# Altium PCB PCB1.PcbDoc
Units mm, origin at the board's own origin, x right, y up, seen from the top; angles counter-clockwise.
Board outline 145 x 75 mm, 2 copper layers (Top Layer, Bottom Layer); 34 components, 27 nets, 127 pads, 4 vias.
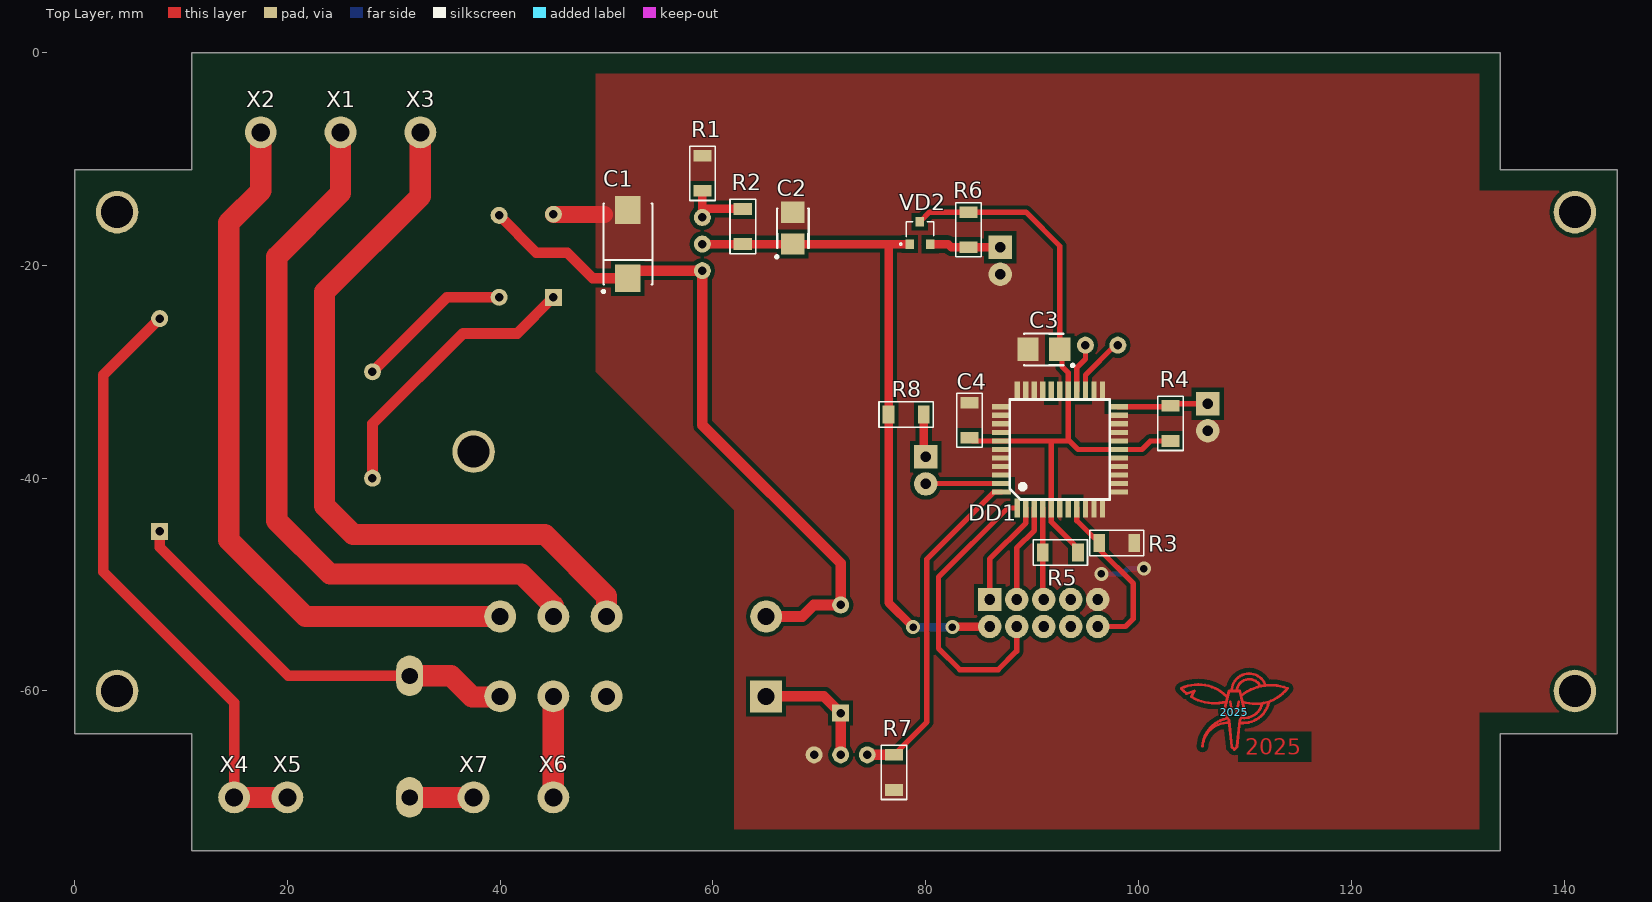
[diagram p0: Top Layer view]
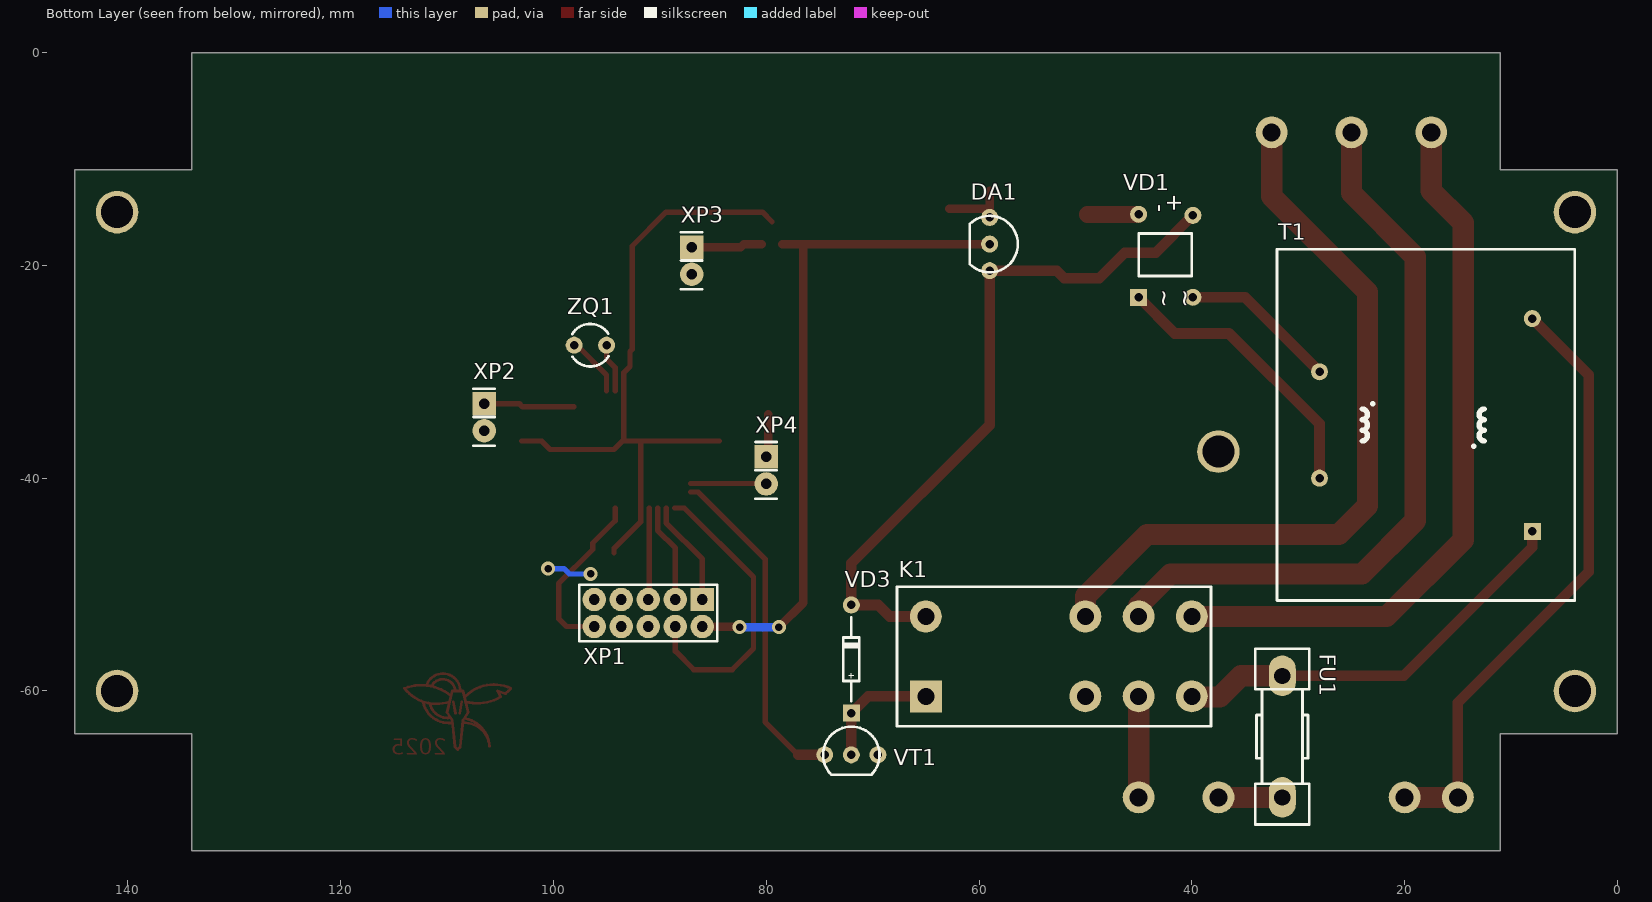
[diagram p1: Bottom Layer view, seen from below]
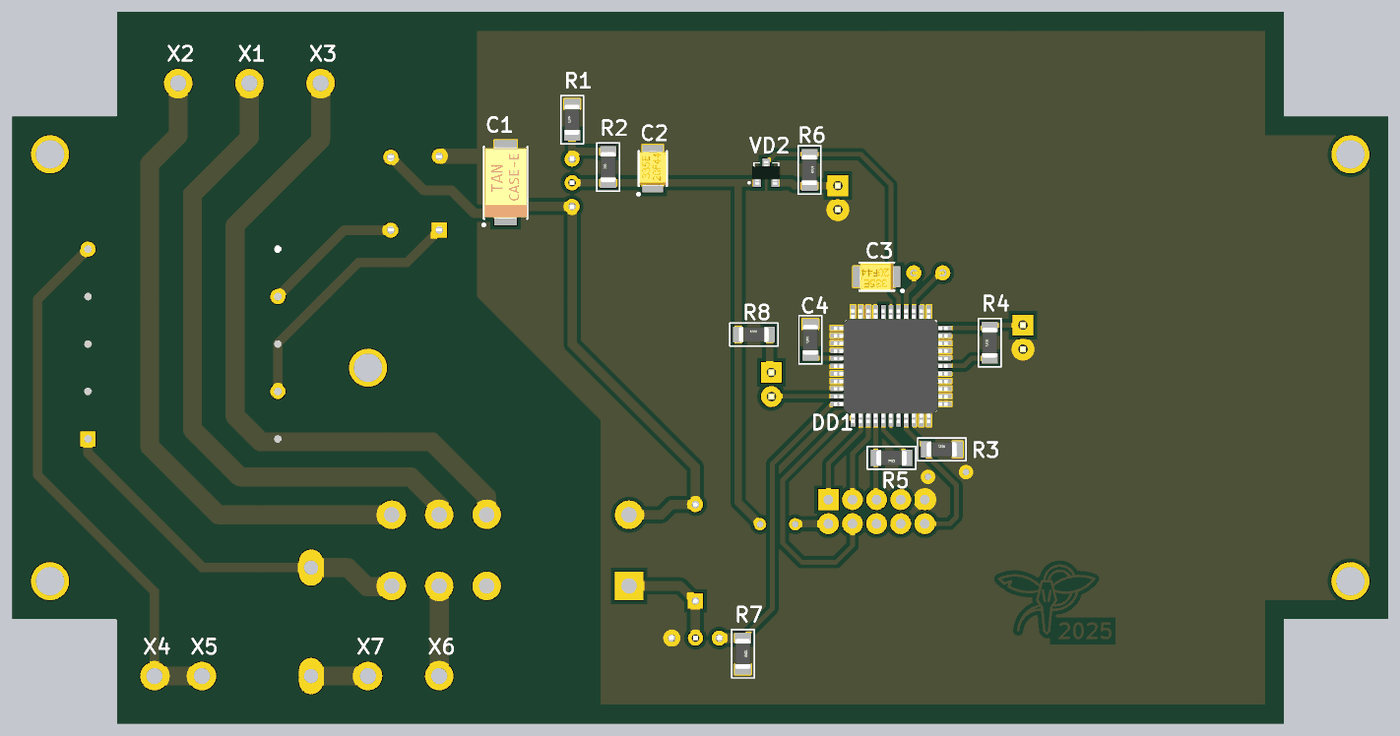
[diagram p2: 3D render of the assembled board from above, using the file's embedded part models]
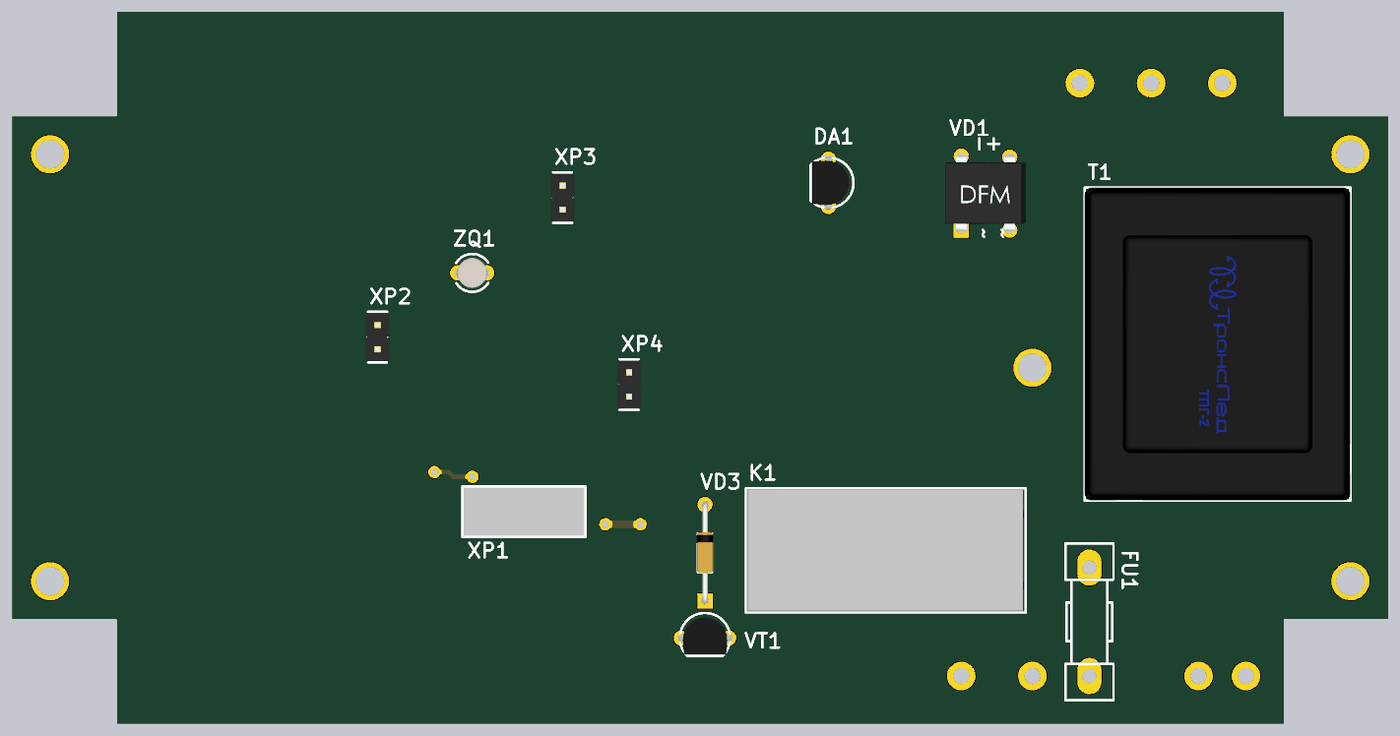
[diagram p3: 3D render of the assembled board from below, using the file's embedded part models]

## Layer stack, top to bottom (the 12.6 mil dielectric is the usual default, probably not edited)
Top Layer: signal copper 0.0356
Dielectric: dielectric 0.32, FR-4, Dk 4.8
Bottom Layer: signal copper 0.0356

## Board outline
0,-64 11,-64 11,-75 134,-75 134,-64 145,-64 145,-11 134,-11 134,0 11,0 11,-11 0,-11

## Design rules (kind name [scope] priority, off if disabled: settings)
Clearance Clearance_poly [InPolygon] p1: gap=0.4
Clearance [All] p2: gap=0.2
ComponentClearance [All] p1: gap=0.25 collisioncheckmode=3 verticalgap=0.25 showdistances=FALSE
DiffPairsRouting [All] p1: maxlimit=1 minlimit=0.2 mostfreqgap=0.8 maxuncoupledlength=10
Height [All] p1: minheight=0 maxheight=45 prefheight=12.5
PolygonConnect [All] p1: connectstyle=Direct reliefconductorwidth=0.35 reliefentries=4 polygonreliefangle="90 Angle"
RoutingVias [All] p1: holewidth=0.8 width=1.2 viastyle="Through Hole" minholewidth=0.7 minwidth=1 maxholewidth=1 maxwidth=1.5
SilkscreenOverComponentPads [All] p1: minsilkscreentomaskgap=0.254
SolderMaskExpansion [All] p1: expansion=0.102
Width [All] p1: maxlimit=3 minlimit=0.3 preferedwidth=0.5
24 further rules are at their usual default settings.

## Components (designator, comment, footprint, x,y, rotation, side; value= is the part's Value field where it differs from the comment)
2025 "2025" "Rat's logo" 109,-62 r0 top
C1 "Type E" "Type E" 52,-18 r90 top
C2 "Type B" "Type B" 67.5,-16.5 r90 top
C3 "Type B" "Type B" 91.1,-27.9 r180 top
C4 "C_1206" RC_1206 84.1,-36.2 r90 top
DA1 "LM317L" TO-92 59,-18 r270 bottom
DD1 "К1946ВМ014" TQFP-44 88.6,-42.8 r90 top
FU1 "Предохранитель" ВП2-1 31.5,-70 r90 bottom
K1 "RP3" RP3 65,-60.5 r0 bottom
R1 "R_1206" RC_1206 59,-13 r90 top
R2 "R_1206" RC_1206 62.8,-18 r90 top
R3 "R_1206" RC_1206 96.3,-46.1 r0 top
R4 "R_1206" RC_1206 103,-36.5 r90 top
R5 "R_1206" RC_1206 94.3,-47 r180 top
R6 "R_1206" RC_1206 84,-15 r270 top
R7 "R_1206" RC_1206 77,-66 r270 top
R8 "R_1206" RC_1206 76.5,-34 r0 top
T1 "ТПК-2" ТПГ-2 8,-45 r0 bottom
VD1 "КД906" DB-1 45,-23 r90 bottom
VD2 "КДШ160БС9" SOT-23 78.5,-18 r0 top
VD3 "КД510" DO-35 72,-57 r90 bottom
VT1 "КП501" TO-92 72,-66 r180 bottom
X1 "Клемма 1,7 мм" "Клемма 1,7 мм" 25,-7.5 r0 top
X2 "Клемма 1,7 мм" "Клемма 1,7 мм" 17.5,-7.5 r0 top
X3 "Клемма 1,7 мм" "Клемма 1,7 мм" 32.5,-7.5 r0 top
X4 "Клемма 1,7 мм" "Клемма 1,7 мм" 15,-70 r0 top
X5 "Клемма 1,7 мм" "Клемма 1,7 мм" 20,-70 r0 top
X6 "Клемма 1,7 мм" "Клемма 1,7 мм" 45,-70 r0 top
X7 "Клемма 1,7 мм" "Клемма 1,7 мм" 37.5,-70 r0 top
XP1 "IDC_progr" IDC-10MS 86,-51.4 r0 bottom
XP2 "Button" PLS-2 106.5,-33 r270 bottom
XP3 "Pow" PLS-2 87,-18.3 r270 bottom
XP4 "LED" PLS-2 80,-38 r270 bottom
ZQ1 "DT-38T" DT-38T 95,-27.5 r90 bottom

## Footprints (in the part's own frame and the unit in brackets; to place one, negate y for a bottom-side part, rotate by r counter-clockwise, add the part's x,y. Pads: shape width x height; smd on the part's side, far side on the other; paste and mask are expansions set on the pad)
DB-1 [mm]
  rect 1.6x1.6 hole 0.8: 1(0,0)
  round 1.6 hole 0.8: 2(0,-5.1) 3(7.7,-5.1) 4(7.8,0)
  silkscreen extent 2,-5 6,0, body extent -0.1,-6.81 7.9,1.7, height 4.75
DO-35 [mm]
  rect 1.6x1.6 hole 0.8: 1(-5.084,0)
  round 1.6 hole 0.8: 2(5.084,0)
  silkscreen extent -3.94,-0.75 3.94,0.75, body extent -5.35,-0.89 5.34,0.86, height 2.15
DT-38T [mm]
  round 1.6 hole 0.8: 1(0,0) 2(0,3.048)
  silkscreen extent -2,-0.18 2,3.23, body extent -1.6,-0.2 1.6,3.25, height 9.77
IDC-10MS [mm]
  rect 2.2x2.2 hole 1: 1(0,0)
  round 2.2 hole 1: 2(0,2.54) 3(2.54,0) 4(2.54,2.54) 5(5.08,0) 6(5.08,2.54) 7(7.62,0) 8(7.62,2.54) 9(10.16,0) 10(10.16,2.54)
  silkscreen extent -1.4,-1.4 11.56,3.94, body extent -1.27,-1.27 11.43,3.81, height 8.54
PLS-2 [mm]
  rect 2.2x2.2 hole 1: 1(0,0)
  round 2.2 hole 1: 2(2.54,0)
  silkscreen extent -1.4,-1 3.94,1, body extent -1.27,-1.27 3.81,1.27, height 8.54
"Rat's logo" [mm]
  Top Layer lines w0.254: -4.516,1.786 cw(c-1.875,5.025) -5,2.25 cw(c-3.402,-1.109) -0.75,1.5 ; -4.5,1.75 -3.75,2 -4,1.5 ; -4.033,1.446 ccw(c-1.875,5.025) -0.75,1 ; -0.8,-0.6 ccw(c-0.153,-3.378) -3,-3.2 cw(c-0.65,-3.35) -0.5,-1 ; -0.4,1 -0.2,-0.1 ; -0.238,2.147 cw(c1.384,2.012) 2.9,2.6 ; 0.2,-0.1 0.4,1 ; 0.239,2.148 cw(c1.394,1.929) 2.395,2.546 ; 0.6,-1 ccw(c0.831,1.445) 3.23,0.923 ; 0.652,1.562 cw(c3.411,-1.797) 5,2.25 cw(c2,4.6) 0.75,1 ; 0.711,-0.52 ccw(c0.937,1.169) 2.6,0.8 ; -1,0 -0.5,2 0.5,2 1,0 0.5,-0.75 0.25,-3.25 0,-3.5 -0.25,-3.25 -0.5,-0.75 -1,0
RC_1206 [mm]
  rect 1.1x1.7 smd: 1(0,0) 2(3.3,0)
  silkscreen extent -0.9,-1.2 4.2,1.2, body extent 0.05,-0.8 3.25,0.8, height 1
RP3 [mm]
  rect 3x3 hole 1.6: 1(0,0)
  round 3 hole 1.6: 2(0,-7.5) 3(-20,0) 4(-15,0) 5(-25,0) 6(-20,-7.5) 7(-15,-7.5) 8(-25,-7.5)
  silkscreen extent -26.8,-10.3 2.7,2.8, body extent -26.5,-10.1 2.5,2.6, height 15.7
SOT-23 [mm]
  rect 0.8x0.9 smd: 1(0,0) 2(1.9,0) 3(0.95,2.1)
  silkscreen extent -0.95,-0.1 2.25,2.1, body extent -0.55,-0.2 2.45,2.3, height 1.05
TO-92 [mm]
  round 1.6 hole 0.8: 1(-2.5,0) 2(0,0) 3(2.5,0)
  silkscreen extent -2.65,-1.88 2.65,2.65, body extent -2.8,-1.75 2.8,2.18, height 9.7
TQFP-44 [mm]
  rect 1.8x0.5 smd: 1(0,0) 2(0,-0.8) 3(0,-1.6) 4(0,-2.4) 5(0,-3.2) 6(0,-4) 7(0,-4.8) 8(0,-5.6) 9(0,-6.4) 10(0,-7.2) 11(0,-8) 23(11,-8) 24(11,-7.2) 25(11,-6.4) 26(11,-5.6) 27(11,-4.8) 28(11,-4) 29(11,-3.2) 30(11,-2.4) 31(11,-1.6) 32(11,-0.8) 33(11,0)
  rect 0.5x1.8 smd: 12(1.5,-9.5) 13(2.3,-9.5) 14(3.1,-9.5) 15(3.9,-9.5) 16(4.7,-9.5) 17(5.5,-9.5) 18(6.3,-9.5) 19(7.1,-9.5) 20(7.9,-9.5) 21(8.7,-9.5) 22(9.5,-9.5) 34(9.5,1.5) 35(8.7,1.5) 36(7.9,1.5) 37(7.1,1.5) 38(6.3,1.5) 39(5.5,1.5) 40(4.7,1.5) 41(3.9,1.5) 42(3.1,1.5) 43(2.3,1.5) 44(1.5,1.5)
  silkscreen extent 0.8,-8.7 10.2,0.7, body extent -0.54,-9.97 11.46,2.03, height 1.1
"Type B" [mm]
  rect 2x2.2 smd: 1(-1.5,0) 2(1.5,0)
  silkscreen extent -2.82,-1.5 1.85,1.62, body extent -1.83,-1.4 1.83,1.4, height 1.89
"Type E" [mm]
  rect 2.6x2.4 smd: 1(-3.2,0) 2(3.2,0)
  silkscreen extent -4.57,-2.3 3.8,2.42, body extent -3.76,-2.25 3.76,2.25, height 4.1
ВП2-1 [mm]
  oval 3.81x2.54 hole 1.508: 1(0,0) 2(11.43,0)
  silkscreen extent -2.54,-2.54 13.97,2.54, body extent -2.42,-2.1 13.88,2.1, height 0.9
"Клемма 1,7 мм" [mm]
  round 3 hole 1.7: 1(0,0)
ТПГ-2 [mm]
  rect 1.6x1.6 hole 0.8: 1(0,0)
  round 1.6 hole 0.8: 5(0,-20) 7(20,-15) 9(20,-5)
  silkscreen extent -4,-26.5 24,6.5, body extent -4,-26.5 24,6.5, height 29.5

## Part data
VD1: library part DB102
VD3: library part 1N4148

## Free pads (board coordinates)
  round 4 hole 3 unplated: 0(4,-60) 0(4,-15) 0(37.5,-37.5) 0(141,-60) 0(141,-15)

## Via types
v1: diameter 1.3, hole 0.7, Top Layer to Bottom Layer, 4 vias

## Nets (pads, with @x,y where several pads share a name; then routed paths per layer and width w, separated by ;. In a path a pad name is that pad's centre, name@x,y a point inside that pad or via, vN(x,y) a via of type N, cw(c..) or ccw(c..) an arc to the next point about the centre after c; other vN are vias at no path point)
GND: C1.2 C2.2 C3.2 C4.2 DD1.6 DD1.9 DD1.10 DD1.11 DD1.12 DD1.13 DD1.14 DD1.15 DD1.16 DD1.18 DD1.19 DD1.20 DD1.21 DD1.23 DD1.24 DD1.28 DD1.30 DD1.31 DD1.32 DD1.33 DD1.34 DD1.35 DD1.36 DD1.37 DD1.39 DD1.40 DD1.41 DD1.42 R1.2 R3.2 R7.2 VD1.4 VT1.3 XP1.9 XP2.2 XP3.2 | length 9
  Top Layer w1.6: VD1.4 49.8,-15.2
  Bottom Layer w0.5: v1(96.5,-49) 98.5,-49 99,-48.5 v1(100.5,-48.5)
NetDA1_1: DA1.1 R1.1 R2.2 | length 6.3
  Top Layer w0.8: DA1.1 R1.1 ; 59,-14.7 R2.2
NetDD1_1: DD1.1 XP1.4 | length 28
  Top Layer w0.5: XP1.4 88.54,-56.26 86.8,-58 83.2,-58 81.2,-56 81.2,-49.3 87.7,-42.8 DD1.1
NetDD1_2: DD1.2 XP1.1 | length 10
  Top Layer w0.5: XP1.1 86,-47.6 89.4,-44.2 DD1.2
NetDD1_3: DD1.3 XP1.3 | length 9.3
  Top Layer w0.5: XP1.3 88.54,-46.56 90.2,-44.9 DD1.3
NetDD1_4: DD1.4 R5.2 XP1.5 | length 8.5
  Top Layer w0.5: XP1.5@91,-51.32 R5.2 DD1.4
NetDD1_8: DD1.8 R3.1 XP1.10 | length 16.2
  Top Layer w0.5: DD1.8 94.2,-44 R3.1 96.3,-46.7 99.5,-49.9 99.5,-53.2 98.76,-53.94 XP1.10
NetDD1_22: DD1.22 R4.2 XP2.1 | length 8.5
  Top Layer w0.5: DD1.22 102.9,-33.3 R4.2 103.2,-33 XP2.1
NetDD1_25: DD1.25 ZQ1.2 | length 5.7
  Top Layer w0.5: DD1.25 95,-30.3 97.8,-27.5 ZQ1.2
NetDD1_26: DD1.26 ZQ1.1 | length 4.6
  Top Layer w0.5: DD1.26 94.2,-29.6 95,-28.8 ZQ1.1
NetDD1_43: DD1.43 XP4.2 | length 7.1
  Top Layer w0.5: XP4.2@80.04,-40.5 DD1.43
NetDD1_44: DD1.44 R7.1 VT1.1 | length 31.8
  Top Layer w0.5: R7.1 80.1,-62.9 80.1,-47.6 86.4,-41.3 DD1.44
  Top Layer w1: VT1.1 R7.1
NetFU1_1: FU1.1 X7.1 | length 6
  Top Layer w2: FU1.1 X7.1
NetFU1_2: FU1.2 K1.5 T1.1 | length 39.3
  Top Layer w1: T1.1 8,-46.5 20.07,-58.57 FU1.2
  Top Layer w2: FU1.2 35.37,-58.57 37.37,-60.57 K1.5@39.93,-60.57
NetK1_1: K1.1 VD3.1 VT1.2 | length 11.6
  Top Layer w1: K1.1 70.417,-60.5 VD3.1 VT1.2
NetK1_3: K1.3 X6.1 | length 9.5
  Top Layer w2: X6.1 K1.3
NetK1_6: K1.6 X1.1 | length 69.3
  Top Layer w2: X1.1 25,-13.2 19,-19.2 19,-44 24,-49 42,-49 45,-52 K1.6
NetK1_7: K1.7 X3.1 | length 70.7
  Top Layer w2: X3.1 32.5,-13.5 23.5,-22.5 23.5,-42.6 26.2,-45.3 44.2,-45.3 50,-51.1 K1.7
NetK1_8: K1.8 X2.1 | length 68
  Top Layer w2: X2.1 17.5,-13 14.5,-16 14.5,-45.8 21.7,-53 K1.8
NetR6_2: R6.2 VD2.2 XP3.1 | length 6.7
  Top Layer w0.8: VD2.2 82.1,-18 82.4,-18.3 R6.2 XP3.1
NetR8_2: R8.2 XP4.1 | length 3.8
  Top Layer w0.8: XP4.1@79.8,-37.8 R8.2
NetT1_5: T1.5 X4.1 X5.1 | length 57.3
  Top Layer w1: T1.5 2.7,-30.3 2.7,-48.8 15,-61.1 X4.1
  Top Layer w2: X4.1 X5.1
NetT1_7: T1.7 VD1.2 | length 14.8
  Top Layer w1: T1.7 35,-23 VD1.2
NetT1_9: T1.9 VD1.1 | length 27
  Top Layer w1: T1.9 28,-34.9 36.5,-26.4 41.6,-26.4 VD1.1
VCC: C2.1 DA1.2 R2.1 R8.1 VD2.1 XP1.2 | length 63.5
  Top Layer w0.8: DA1.2 R2.1 VD2.1 ; 76.5,-18.1 R8.1 76.5,-51.7 v1(78.8,-54) ; v1@82.56,-53.94 XP1.2
  Bottom Layer w0.8: v1(78.8,-54) v1(82.5,-54)
VH: C1.1 DA1.3 K1.2 VD1.3 VD3.2 | length 66.1
  Top Layer w1: VD1.3 43.4,-18.8 46.3,-18.8 48.7,-21.2 C1.1 52.7,-20.5 DA1.3 59,-35 72,-48 VD3.2 69.484,-51.917 68.4,-53 K1.2
VMCU: C3.1 C4.1 DD1.5 DD1.17 DD1.27 DD1.38 R4.1 R5.1 R6.1 VD2.3 | length 64.2
  Top Layer w0.5: VD2.3 80.35,-15 R6.1 89.4,-15 92.6,-18.2 C3.1 92.8,-28.1 92.8,-29.5 93.4,-30.1 DD1.27 93.4,-36.4 ; C4.1@84.4,-36.5 DD1.38 93.5,-36.5 94.3,-37.3 DD1.17 100.3,-37.3 101.1,-36.5 R4.1 ; 91.8,-36.5 DD1.5 91.8,-44.1 94.3,-46.6 R5.1
pads on no net: DD1.7 DD1.29 K1.4 XP1.6 XP1.7 XP1.8

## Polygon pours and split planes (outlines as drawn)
GND on Top Layer "Top Layer-GND" (solid, pour order 2): 62,-73 62,-44 62,-43 49,-30 49,-2 132,-2 132,-13 143,-13 143,-62 132,-62 132,-73

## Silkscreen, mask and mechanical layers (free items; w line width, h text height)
Mechanical 32:
  the board outline again, w0.5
